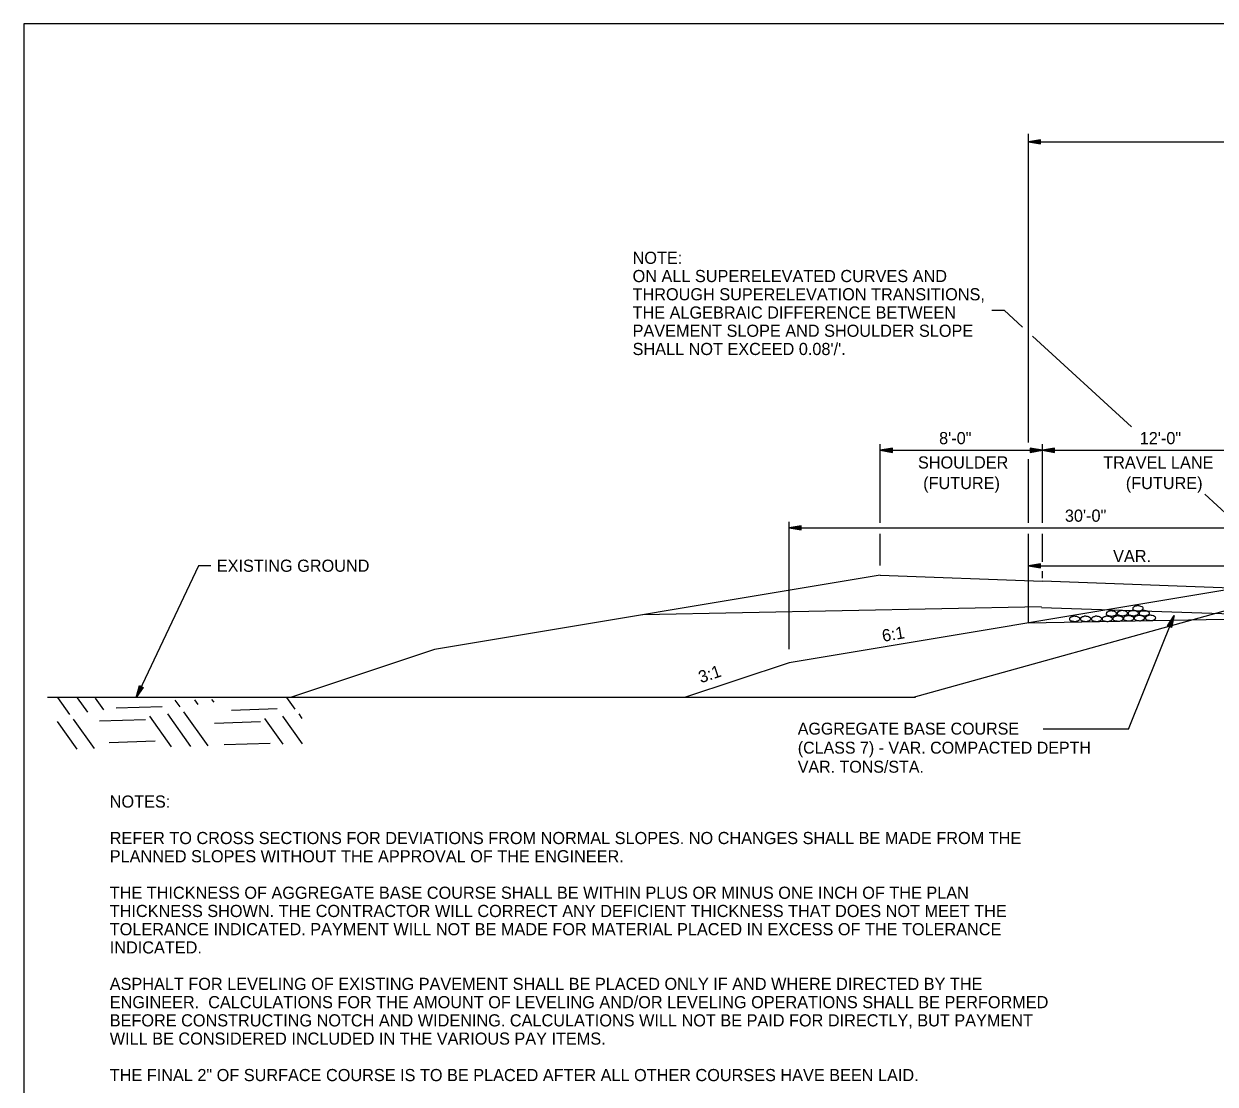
# Model space of a CAD drawing. Extents: x 1461846 to 1462006, y 1686171 to 1686805.
# Drawn here: x 1461846.4 to 1461905.1, y 1686620.6 to 1686672.9 of the extents above; entities that cross this region are included whole.
import ezdxf

# ---------------------------------------------------------------- set-up
doc = ezdxf.new("R2010")
doc.units = 0
for name, color, linetype in [('1', 7, 'Continuous'), ('10', 7, 'Continuous'), ('19', 7, 'Continuous'), ('20', 7, 'Continuous'), ('R_Draft', 7, 'Continuous')]:
    doc.layers.add(name, color=color, linetype=linetype)

# ---------------------------------------------------------------- blocks, each defined once
blk = doc.blocks.new('ROCKS')
at = {"layer": '1'}
blk.add_spline([(0.013, 0.06), (0.053, 0.053), (0.107, 0.033), (0.133, 0.013), (0.133, -0.007), (0.12, -0.033), (0.107, -0.04), (0.073, -0.053), (0.033, -0.067), (0.013, -0.067), (-0.02, -0.06), (-0.06, -0.053), (-0.087, -0.047), (-0.113, -0.02), (-0.113, -0.007), (-0.107, 0.02), (-0.087, 0.033), (-0.067, 0.047), (-0.033, 0.053), (-0.02, 0.06), (0.013, 0.06)], degree=3, dxfattribs=at)

msp = doc.modelspace()

# ---------------------------------------------------------------- linework, layer by layer
at = {"layer": '10'}
for p, q in [((1461846.353, 1686672.939), (1461846.353, 1686568.707)), ((1461964.759, 1686672.939), (1461846.353, 1686672.939))]:
    msp.add_line(p, q, dxfattribs=at)
at = {"layer": '19'}
for p, q in [((1461894.13, 1686658.8), (1461894.73, 1686658.8)), ((1461894.73, 1686658.8), (1461895.644, 1686657.962)), ((1461896.13, 1686657.516), (1461901.009, 1686653.042)), ((1461904.634, 1686649.718), (1461908.455, 1686646.215)), ((1461884.721, 1686648.168), (1461884.121, 1686648.063)), ((1461884.121, 1686648.063), (1461914.121, 1686648.063)), ((1461884.121, 1686648.063), (1461884.721, 1686647.958)), ((1461884.721, 1686648.113), (1461884.281, 1686648.078)), ((1461884.281, 1686648.048), (1461884.721, 1686648.008)), ((1461884.721, 1686647.958), (1461884.721, 1686648.168)), ((1461888.621, 1686645.72), (1461866.621, 1686642.053)), ((1461888.621, 1686645.72), (1461896.621, 1686645.424)), ((1461906.121, 1686645.072), (1461884.121, 1686641.406)), ((1461896.568, 1686644.159), (1461876.896, 1686643.766)), ((1461896.568, 1686644.134), (1461910.871, 1686643.648)), ((1461900.87, 1686638.122), (1461903.12, 1686643.737)), ((1461902.8, 1686643.22), (1461903.12, 1686643.737)), ((1461903.12, 1686643.737), (1461902.993, 1686643.141)), ((1461910.871, 1686643.648), (1461895.93, 1686643.349)), ((1461902.993, 1686643.141), (1461902.8, 1686643.22)), ((1461902.846, 1686643.202), (1461903.045, 1686643.595)), ((1461903.072, 1686643.585), (1461902.945, 1686643.164)), ((1461866.621, 1686642.053), (1461859.519, 1686639.686)), ((1461884.121, 1686641.406), (1461878.961, 1686639.686)), ((1461848.616, 1686638.852), (1461848.034, 1686639.686)), ((1461849.509, 1686638.966), (1461849.004, 1686639.672)), ((1461850.301, 1686639.077), (1461849.895, 1686639.659)), ((1461854.063, 1686639.225), (1461853.829, 1686639.558)), ((1461854.956, 1686639.338), (1461854.784, 1686639.579)), ((1461855.748, 1686639.45), (1461855.638, 1686639.597)), ((1461859.743, 1686639.112), (1461859.337, 1686639.686)), ((1461853.175, 1686639.232), (1461850.915, 1686639.166)), ((1461855.448, 1686637.294), (1461854.255, 1686638.987)), ((1461858.853, 1686639.13), (1461856.595, 1686639.054)), ((1461848.985, 1686637.145), (1461848.016, 1686638.504)), ((1461849.84, 1686637.164), (1461848.808, 1686638.615)), ((1461852.36, 1686638.584), (1461850.091, 1686638.516)), ((1461853.639, 1686637.255), (1461852.569, 1686638.762)), ((1461854.594, 1686637.276), (1461853.462, 1686638.876)), ((1461858.029, 1686638.481), (1461855.77, 1686638.404)), ((1461859.147, 1686637.383), (1461858.249, 1686638.65)), ((1461860.102, 1686637.404), (1461859.142, 1686638.764)), ((1461860.094, 1686638.653), (1461859.934, 1686638.875)), ((1461900.87, 1686638.122), (1461896.66, 1686638.122)), ((1461852.828, 1686637.525), (1461850.57, 1686637.448)), ((1461858.508, 1686637.413), (1461856.238, 1686637.345))]:
    msp.add_line(p, q, dxfattribs=at)
msp.add_lwpolyline([(1461955.621, 1686643.241), (1461896.621, 1686645.424)], dxfattribs=at)
at = {"layer": '20'}
for p, q in [((1461895.93, 1686652.274), (1461895.93, 1686667.516)), ((1461896.53, 1686667.218), (1461895.93, 1686667.113)), ((1461896.53, 1686667.008), (1461896.53, 1686667.218)), ((1461895.93, 1686667.113), (1461956.082, 1686667.113)), ((1461895.93, 1686667.113), (1461896.53, 1686667.008)), ((1461896.53, 1686667.163), (1461896.09, 1686667.128)), ((1461896.09, 1686667.098), (1461896.53, 1686667.058)), ((1461888.621, 1686648.302), (1461888.621, 1686652.19)), ((1461889.221, 1686651.995), (1461888.621, 1686651.89)), ((1461889.221, 1686651.94), (1461888.781, 1686651.905)), ((1461889.221, 1686651.785), (1461889.221, 1686651.995)), ((1461896.021, 1686651.995), (1461896.021, 1686651.785)), ((1461896.621, 1686651.89), (1461896.021, 1686651.995)), ((1461896.461, 1686651.905), (1461896.021, 1686651.94)), ((1461896.621, 1686648.302), (1461896.621, 1686652.19)), ((1461897.221, 1686651.995), (1461896.621, 1686651.89)), ((1461897.221, 1686651.94), (1461896.781, 1686651.905)), ((1461897.221, 1686651.785), (1461897.221, 1686651.995)), ((1461888.621, 1686651.89), (1461896.621, 1686651.89)), ((1461888.621, 1686651.89), (1461889.221, 1686651.785)), ((1461888.781, 1686651.875), (1461889.221, 1686651.835)), ((1461895.93, 1686648.302), (1461895.93, 1686651.458)), ((1461896.021, 1686651.785), (1461896.621, 1686651.89)), ((1461896.021, 1686651.835), (1461896.461, 1686651.875)), ((1461896.621, 1686651.89), (1461908.621, 1686651.89)), ((1461896.621, 1686651.89), (1461897.221, 1686651.785)), ((1461896.781, 1686651.875), (1461897.221, 1686651.835)), ((1461884.121, 1686642.078), (1461884.121, 1686648.363)), ((1461888.621, 1686646.196), (1461888.621, 1686647.763)), ((1461895.93, 1686643.349), (1461895.93, 1686647.763)), ((1461896.621, 1686646.381), (1461896.621, 1686647.763)), ((1461896.53, 1686646.29), (1461895.93, 1686646.185)), ((1461895.93, 1686646.185), (1461906.121, 1686646.185)), ((1461895.93, 1686646.185), (1461896.53, 1686646.08)), ((1461896.53, 1686646.235), (1461896.09, 1686646.2)), ((1461896.09, 1686646.17), (1461896.53, 1686646.13)), ((1461896.53, 1686646.08), (1461896.53, 1686646.29)), ((1461896.621, 1686645.572), (1461896.621, 1686645.922))]:
    msp.add_line(p, q, dxfattribs=at)
at = {"layer": 'R_Draft'}
for p, q in [((1461851.899, 1686639.686), (1461852.061, 1686640.273)), ((1461852.25, 1686640.183), (1461851.899, 1686639.686)), ((1461851.958, 1686639.834), (1461852.108, 1686640.245)), ((1461852.207, 1686640.2), (1461851.982, 1686639.825)), ((1461852.061, 1686640.273), (1461852.25, 1686640.183)), ((1461890.357, 1686639.686), (1461847.527, 1686639.686))]:
    msp.add_line(p, q, dxfattribs=at)
for points in [[(1461855.576, 1686646.193), (1461854.976, 1686646.193), (1461851.899, 1686639.686)], [(1462000.252, 1686643.294), (1461985.479, 1686642.773), (1461972.442, 1686642.427), (1461966.445, 1686641.94), (1461956.315, 1686639.45), (1461938.121, 1686642.877), (1461934.871, 1686643.842), (1461929.37, 1686643.781), (1461912.792, 1686644.39), (1461910.871, 1686644.73), (1461906.121, 1686644.095), (1461890.249, 1686639.689)]]:
    msp.add_lwpolyline(points, dxfattribs=at)

# ---------------------------------------------------------------- block references
at = {"layer": '19', "xscale": 2.061136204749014, "yscale": 2.061136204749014}
for p in [(1461898.19, 1686643.574), (1461898.728, 1686643.574), (1461899.272, 1686643.574), (1461899.799, 1686643.574), (1461900.007, 1686643.838), (1461900.33, 1686643.589), (1461900.549, 1686643.854), (1461900.854, 1686643.602), (1461901.083, 1686643.854), (1461901.32, 1686644.093), (1461901.388, 1686643.612), (1461901.625, 1686643.854), (1461901.933, 1686643.621)]:
    msp.add_blockref('ROCKS', p, dxfattribs=at)

# ---------------------------------------------------------------- texts
at = {"layer": '10'}
for s, p in [('8\'-0"', (1461891.522, 1686652.19)), ('12\'-0"', (1461901.423, 1686652.19)), ('SHOULDER', (1461890.478, 1686650.99)), ('TRAVEL LANE', (1461899.621, 1686650.99)), ('(FUTURE)', (1461890.736, 1686649.974)), ('(FUTURE)', (1461900.736, 1686649.974))]:
    msp.add_text(s, height=0.6, dxfattribs=at).set_placement(p)
at = {"layer": '19'}
for s, p in [('AGGREGATE BASE COURSE', (1461884.548, 1686637.856)), ('(CLASS 7) - VAR. COMPACTED DEPTH', (1461884.548, 1686636.916)), ('VAR. TONS/STA.', (1461884.548, 1686635.976))]:
    msp.add_text(s, height=0.59001, rotation=360, dxfattribs=at).set_placement(p)
at = {"layer": 'R_Draft'}
for s, p in [('NOTE:', (1461876.395, 1686661.091)), ('ON ALL SUPERELEVATED CURVES AND', (1461876.395, 1686660.191)), ('THROUGH SUPERELEVATION TRANSITIONS,', (1461876.395, 1686659.291)), ('THE ALGEBRAIC DIFFERENCE BETWEEN', (1461876.395, 1686658.391)), ('PAVEMENT SLOPE AND SHOULDER SLOPE', (1461876.395, 1686657.491)), ("SHALL NOT EXCEED 0.08'/'.", (1461876.395, 1686656.591)), ('30\'-0"', (1461897.729, 1686648.363)), ('EXISTING GROUND', (1461855.876, 1686645.893)), ('NOTES:', (1461850.593, 1686634.252)), ('REFER TO CROSS SECTIONS FOR DEVIATIONS FROM NORMAL SLOPES. NO CHANGES SHALL BE MADE FROM THE ', (1461850.593, 1686632.452)), ('PLANNED SLOPES WITHOUT THE APPROVAL OF THE ENGINEER.', (1461850.593, 1686631.552)), ('THE THICKNESS OF AGGREGATE BASE COURSE SHALL BE WITHIN PLUS OR MINUS ONE INCH OF THE PLAN ', (1461850.593, 1686629.752)), ('THICKNESS SHOWN. THE CONTRACTOR WILL CORRECT ANY DEFICIENT THICKNESS THAT DOES NOT MEET THE ', (1461850.593, 1686628.852)), ('TOLERANCE INDICATED. PAYMENT WILL NOT BE MADE FOR MATERIAL PLACED IN EXCESS OF THE TOLERANCE ', (1461850.593, 1686627.952)), ('INDICATED.', (1461850.593, 1686627.052)), ('ASPHALT FOR LEVELING OF EXISTING PAVEMENT SHALL BE PLACED ONLY IF AND WHERE DIRECTED BY THE ', (1461850.593, 1686625.252)), ('ENGINEER.  CALCULATIONS FOR THE AMOUNT OF LEVELING AND/OR LEVELING OPERATIONS SHALL BE PERFORMED ', (1461850.593, 1686624.352)), ('BEFORE CONSTRUCTING NOTCH AND WIDENING. CALCULATIONS WILL NOT BE PAID FOR DIRECTLY, BUT PAYMENT ', (1461850.593, 1686623.452)), ('WILL BE CONSIDERED INCLUDED IN THE VARIOUS PAY ITEMS.', (1461850.593, 1686622.552)), ('THE FINAL 2" OF SURFACE COURSE IS TO BE PLACED AFTER ALL OTHER COURSES HAVE BEEN LAID. ', (1461850.593, 1686620.752))]:
    msp.add_text(s, height=0.6, dxfattribs=at).set_placement(p)
for s, rotation, p in [('VAR.', 360, (1461900.109, 1686646.368)), ('6:1', 9.46232, (1461888.757, 1686642.434)), ('3:1', 18.43495, (1461879.765, 1686640.388))]:
    msp.add_text(s, height=0.6, rotation=rotation, dxfattribs=at).set_placement(p)

doc.saveas('drawing.dxf')
